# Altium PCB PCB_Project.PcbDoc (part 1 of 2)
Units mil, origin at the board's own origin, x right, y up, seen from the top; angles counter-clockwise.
Board outline 2079.64 x 1653.54 mil, 2 copper layers (Top Layer, Bottom Layer), stack 62 mil thick; 65 components, 34 nets, 154 pads, 107 vias.
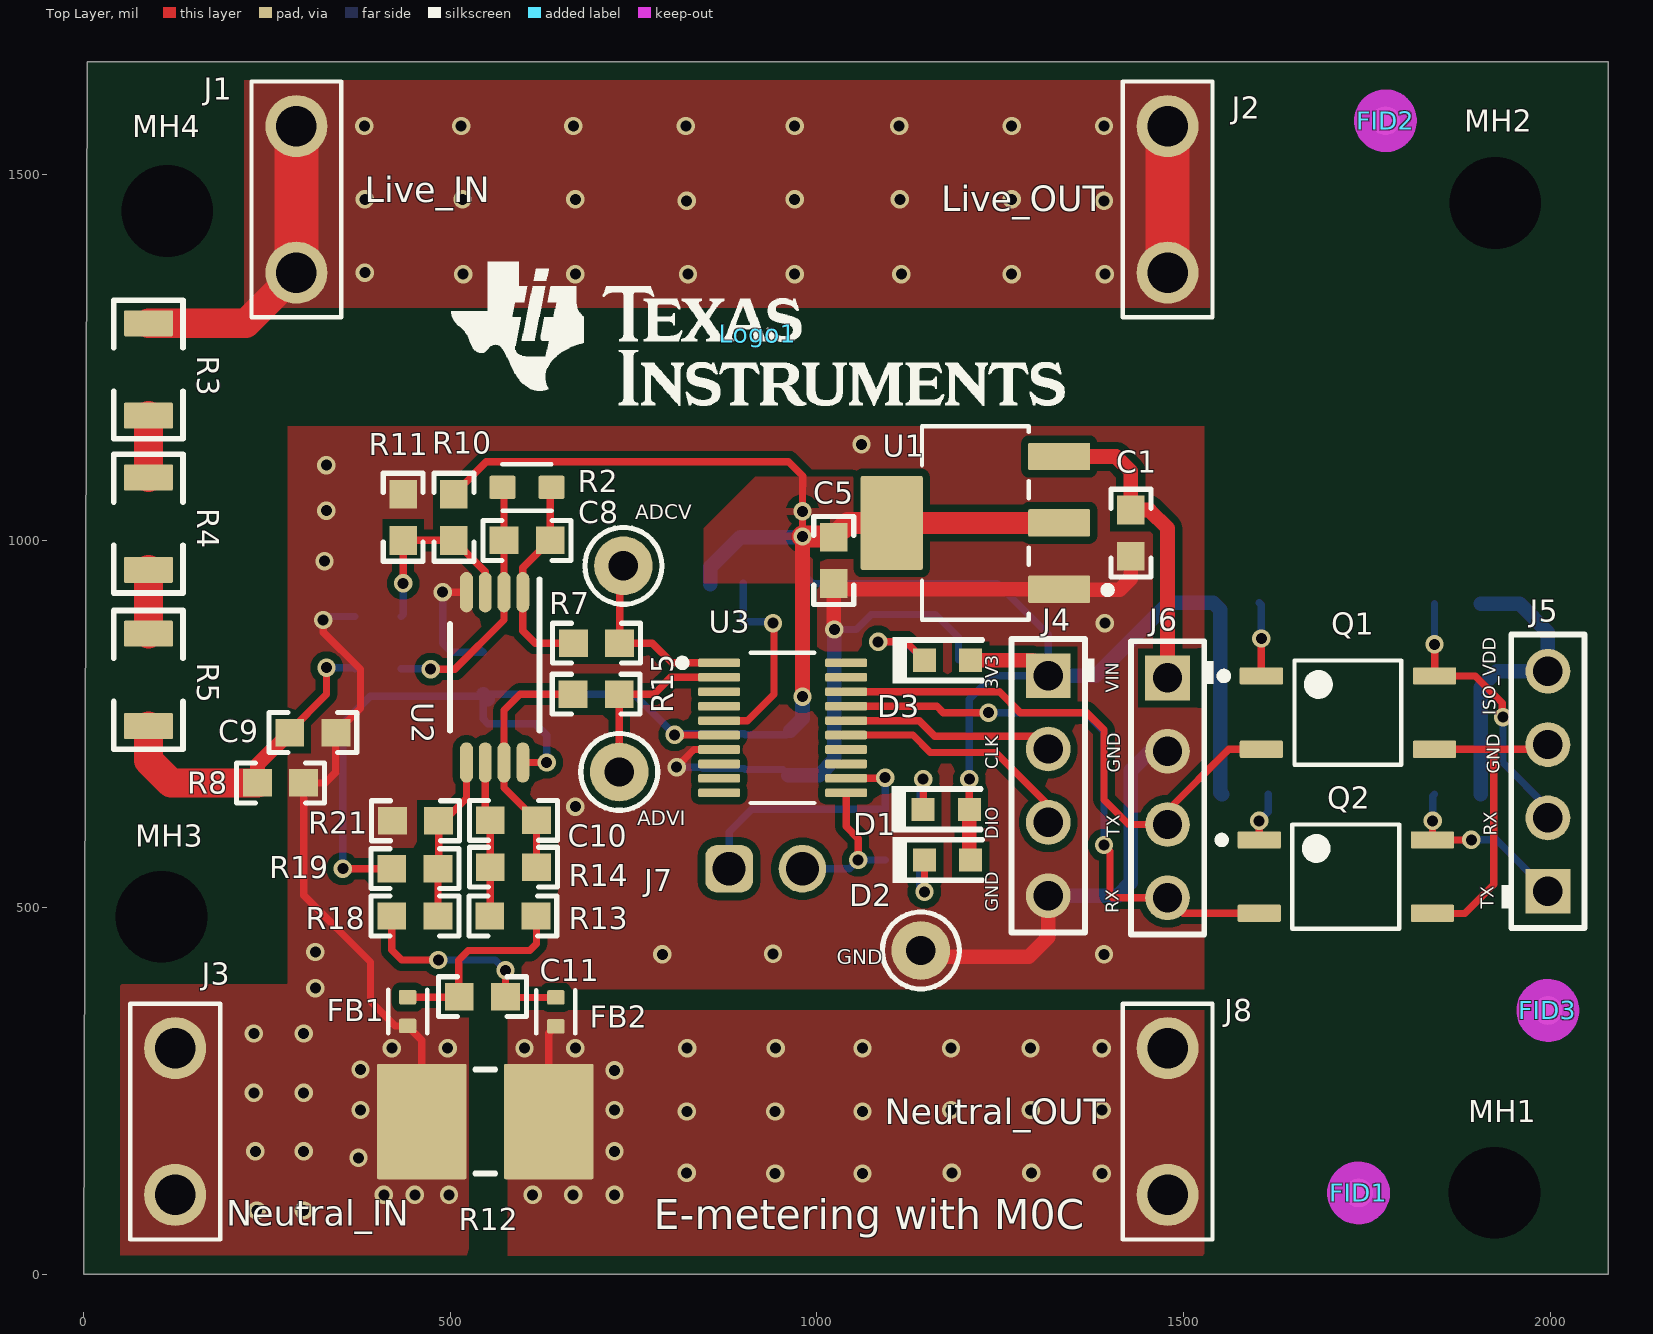
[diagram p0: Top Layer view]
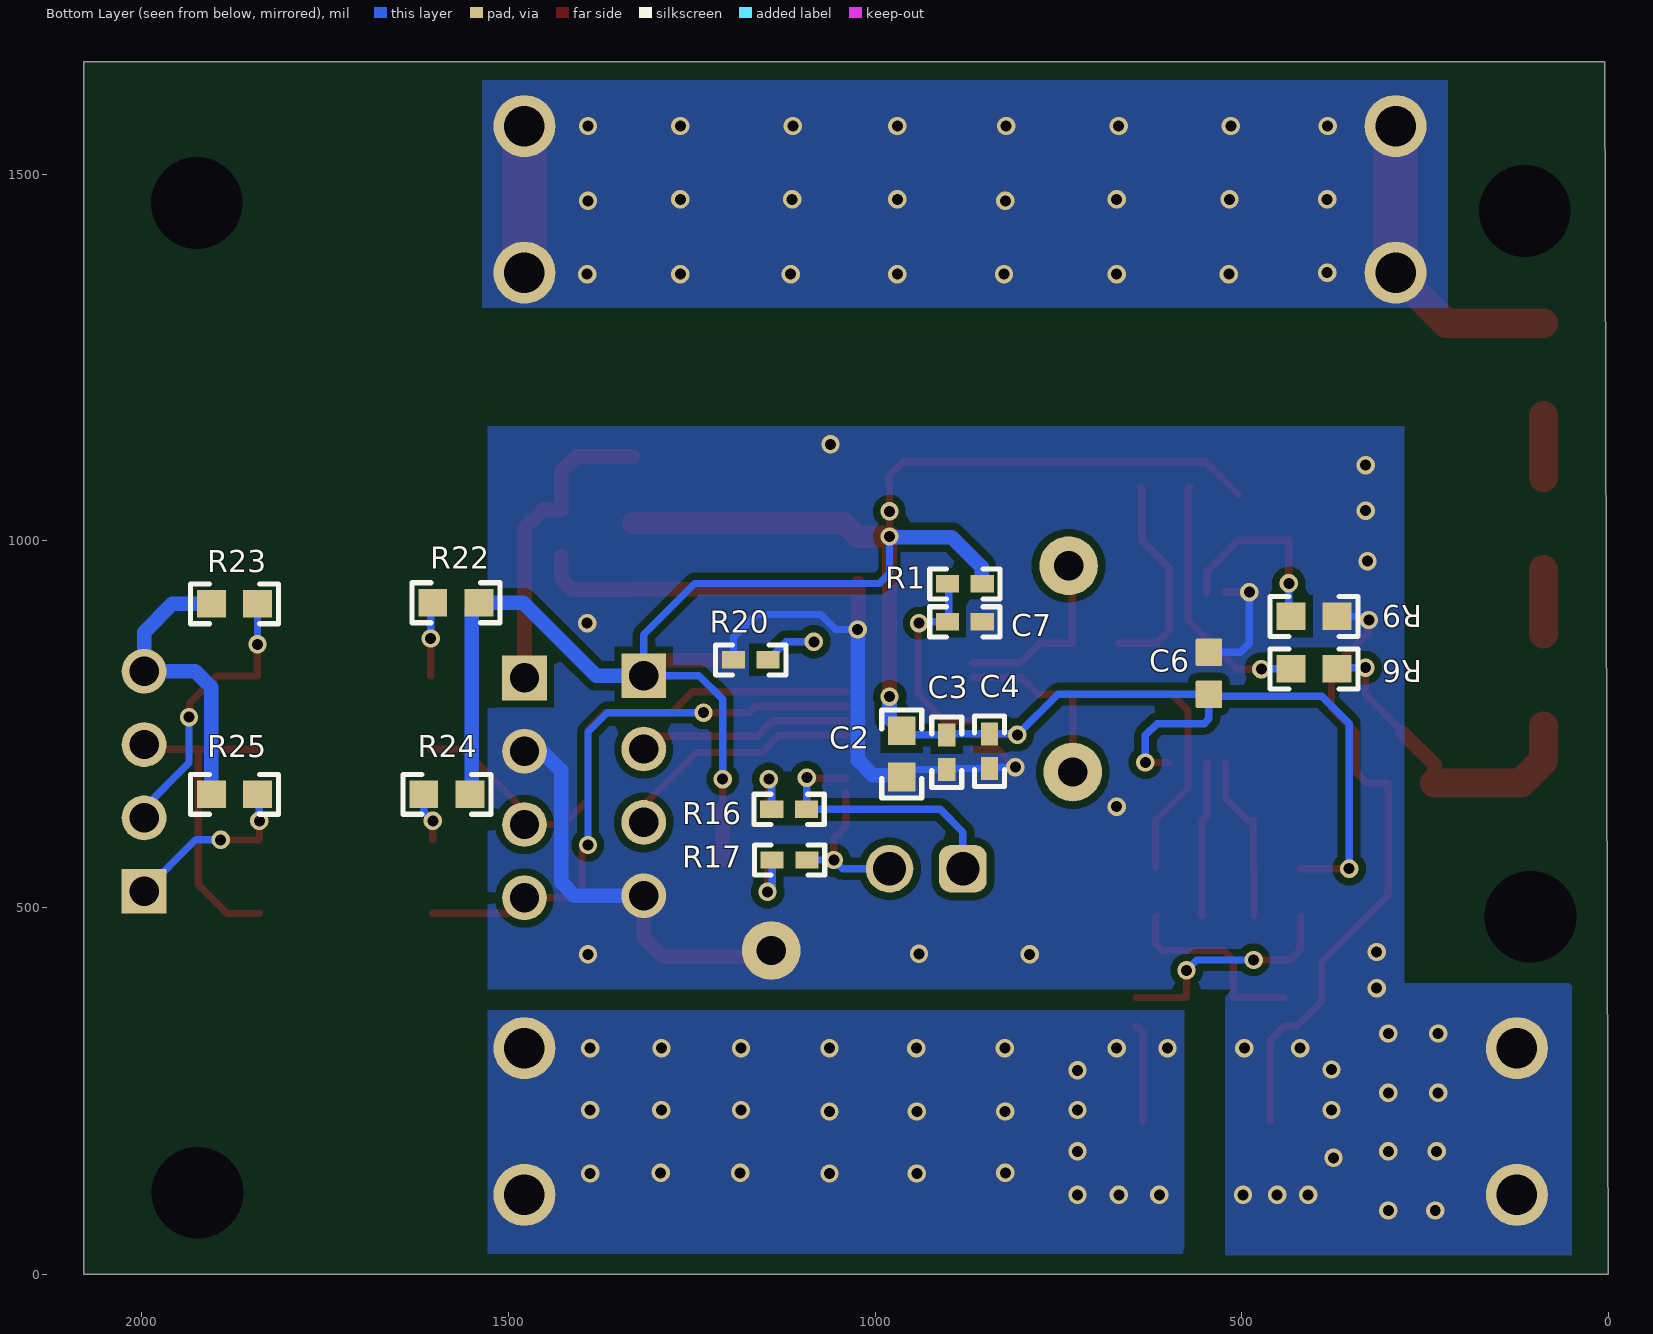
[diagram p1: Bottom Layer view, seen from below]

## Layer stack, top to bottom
Top Solder: solder mask 0.4, Solder Resist, Dk 3.5
Top Layer: signal copper 1.4
Dielectric1: core 59.2, FR-4 High Tg, Dk 4.8
Bottom Layer: signal copper 1.4
Bottom Solder: solder mask 0.4, Solder Resist, Dk 3.5

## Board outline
0,0 4.92,1653.54 2079.64,1653.54 2079.64,0

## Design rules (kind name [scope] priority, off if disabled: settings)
AcuteAngle [All] p1: minimum=4.50000000000000E+0001 checktracksonly=FALSE
AssemblyTestPointUsage [All] p1: valid=2
BoardOutlineClearance BoardOutlineClearance_MountingHoles [OnCopper and InComponentClass('Mounting Holes')] p1: gap=39.37 ignorepadtopadclearanceinfootprint=FALSE
BoardOutlineClearance BoardOutlineClearance_Poly [OnCopper and IsPoly] p2: gap=25 ignorepadtopadclearanceinfootprint=FALSE
BoardOutlineClearance [OnCopper and Not InComponentClass('Logo') and not InComponentClass('FiducialMark') and not InRegion(1000,500,4000,800) and not InPoly] p3: gap=40 ignorepadtopadclearanceinfootprint=FALSE
Clearance Clearance_Keepouts [((IsTrack Or IsArc) And Not InPoly) And IsFree and IsKeepOut vs ((IsTrack Or IsArc) And Not InPoly) And IsFree and IsKeepOut] p1: gap=0 ignorepadtopadclearanceinfootprint=FALSE
Clearance Clearance_Poly [InPolygon] p2: gap=10 ignorepadtopadclearanceinfootprint=TRUE
Clearance Clearance_FiducialMark [IsKeepOut and InComponentClass('FiducialMark') vs IsPad and InComponentClass('FiducialMark')] p3: gap=0 ignorepadtopadclearanceinfootprint=FALSE
Clearance [All] p4: gap=7.87 ignorepadtopadclearanceinfootprint=TRUE
ComponentClearance ComponentClearance_MountingHoles_FiducialMarks [InComponentClass('Mounting Holes') vs InComponentClass('FiducialMark')] p1: gap=50 collisioncheckmode=3 verticalgap=10 showdistances=FALSE
ComponentClearance ComponentClearance_Shunt [InComponentClass('Header') vs InComponentClass('Shunt')] p2: gap=0 collisioncheckmode=3 verticalgap=0 showdistances=FALSE
ComponentClearance ComponentClearance_Logo [InComponentClass('Logo')] p3: gap=30 collisioncheckmode=3 verticalgap=10 showdistances=FALSE
ComponentClearance ComponentClearance_ScrewToNut [(HasFootprint('NY PMS 440 0025 PH')) vs (HasFootprint('Keystone_1902C'))] p4: gap=5 collisioncheckmode=3 verticalgap=10 showdistances=FALSE
ComponentClearance ComponentClearance_MountingHoles [InComponentClass('Mounting Holes')] p5: gap=100 collisioncheckmode=3 verticalgap=100000 showdistances=FALSE
ComponentClearance ComponentClearance_SmallPassives [HasFootprint('0201*') or HasFootprint('0402*') or HasFootprint('0508') or HasFootprint('0603*') or HasFootprint('0612') or HasFootprint('0805*') or HasFootprint('0815*') or HasFootprint('0830*') or HasFootprint('1206*') or HasFootprint('1210*') or HasFootprint('1808*') or HasFootprint('1812*') or HasFootprint('1825*') or HasFootprint('2010*') or HasFootprint('2220*') or HasFootprint('2225*') or HasFootprint('2512*') or HasFootprint('2728*') or HasFootprint('3518*') vs HasFootprint('0201*') or HasFootprint('0402*') or HasFootprint('0508') or HasFootprint('0603*') or HasFootprint('0612') or HasFootprint('0805*') or HasFootprint('0815*') or HasFootprint('0830*') or HasFootprint('1206*') or HasFootprint('1210*') or HasFootprint('1808*') or HasFootprint('1812*') or HasFootprint('1825*') or HasFootprint('2010*') or HasFootprint('2220*') or HasFootprint('2225*') or HasFootprint('2512*') or HasFootprint('2728*') or HasFootprint('3518*')] p6: gap=14.96 collisioncheckmode=3 verticalgap=10 showdistances=FALSE
ComponentClearance ComponentClearance_THtoSMT [IsThruComponent vs IsSMTComponent] p7: gap=30 collisioncheckmode=3 verticalgap=30 showdistances=FALSE
ComponentClearance ComponentClearance_THtoTH [IsThruComponent vs IsThruComponent] p8: gap=20 collisioncheckmode=3 verticalgap=30 showdistances=FALSE
ComponentClearance [All] p9: gap=20 collisioncheckmode=3 verticalgap=10 showdistances=FALSE
DiffPairsRouting [All] p1: maxlimit=100 minlimit=10 mostfreqgap=10 toplayer_minwidth=15 toplayer_maxwidth=15 toplayer_prefwidth=15 bottomlayer_minwidth=15 bottomlayer_maxwidth=15 bottomlayer_prefwidth=15 maxuncoupledlength=1000
FabricationTestPointUsage TestPointUsage [All] p1: valid=2 allowmultiple=FALSE
FabricationTestpoint Testpoint [All] p1: side=3 testpointundercomponent=TRUE minsize=40 maxsize=100 preferedsize=60 minholesize=0 maxholesize=40 preferedholesize=32 testpointgrid=1 allowsidetop=TRUE allowsidebottom=TRUE usegrid=TRUE gridtolerance=0.01
FanoutControl Fanout_LCC [IsLCC] p1: bgadir=Out bgaviamode=Centered fanoutstyle=Auto fanoutdirection=Alternating viagrid=1 // Fanout_LCC (Default Rule)
FanoutControl Fanout_BGA [IsBGA] p2: bgadir=Out bgaviamode=Centered fanoutstyle=Auto fanoutdirection=Alternating viagrid=1 // Fanout_BGA (Default Rule)
FanoutControl Fanout_Default [All] p4: bgadir=Out bgaviamode=Centered fanoutstyle=Auto fanoutdirection=Alternating viagrid=1 // Fanout_Default (Default Rule)
FanoutControl Fanout_Small [(CompPinCount < 5)] p5: bgadir=Out bgaviamode=Centered fanoutstyle=Auto fanoutdirection=OutThenIn viagrid=1 // Fanout_Small (Default Rule)
HoleSize [All] p1: absolutevalues=TRUE maxlimit=251 minlimit=5 maxpercent=80.000 minpercent=20.000
MinimumAnnularRing MinimumAnnularRing_ThermalPadVias [IsVia and InAnyComponent] p1: minimumring=4
MinimumAnnularRing [All] p2: minimumring=4
MinimumSolderMaskSliver MinimumSolderMaskSliver_Logo [InComponentClass('Logo') vs InComponentClass('Logo')] p1: minsoldermaskwidth=0.7
MinimumSolderMaskSliver [All] p2: minsoldermaskwidth=3.94
PlaneConnect [All] p1: planeconnectstyle=Relief reliefexpansion=10 reliefentries=4 reliefconductorwidth=10 reliefairgap=10
PolygonConnect [All] p1: connectstyle=Direct reliefconductorwidth=10 reliefentries=4 polygonreliefangle="90 Angle" airgapwidth=10
RoutingVias ThermalPadVias [IsVia and InAnyComponent] p1: holewidth=7.87 width=19.68 viastyle="Through Hole" minholewidth=7.87 minwidth=19.68 maxholewidth=12.99 maxwidth=23.62
RoutingVias [All] p2: holewidth=15 width=25 viastyle="Through Hole" minholewidth=15 minwidth=25 maxholewidth=15 maxwidth=25
SilkToBoardRegionClearance [Not ((IsComment or IsDesignator) And (Hide <> 'False')) and not InRegion(1000,500,4000,800)] p1:
SilkToSilkClearance SilkToSilkClearance_Pb-FreeLogo [(HasFootprint('Pb-Free_Overlay_Medium') OR HasFootprint('Pb-Free_Overlay_Small')) vs (HasFootprint('Pb-Free_Overlay_Medium') OR HasFootprint('Pb-Free_Overlay_Small'))] p1: silktosilkclearance=0
SilkToSilkClearance [All] p2: silktosilkclearance=0
SilkToSolderMaskClearance SilkToComponentPadClearance [(IsPad or IsFill or IsRegion) and InAnycomponent] p1: minsilkscreentomaskgap=0 clearancetoexposedcopper=TRUE
SilkToSolderMaskClearance "Silk to Solder Mask Opening" [All] p2: minsilkscreentomaskgap=0 clearancetoexposedcopper=FALSE
SolderMaskExpansion [All] p1: expansion=1.97 istentingtop=TRUE
UnRoutedNet [All] p1: checkbadconnections=TRUE
Width [All] p1: maxlimit=100 minlimit=6 preferedwidth=10 checkconnectedcopper=TRUE
14 further rules are at their usual default settings.

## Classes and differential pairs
component class PCB_Project_BlankSheet: ADCI ADCV C1 C2 C3 C4 C5 C6 C7 C8 C9 C10 C11 D1 D2 D3 FB1 FB2 GND J1 J2 J3 J4 J5 J6 J7 J8 Q1 Q2 R1 R2 R3 R4 R5 R6 R7 R8 R9 R10 R11 R12 R13 R14 R15 R16 R17 R18 R19 R20 R21 R22 R23 R24 R25 U1 U2 U3
component class Header: J4 J5 J6 J7
component class FiducialMark: FID1 FID2 FID3
component class PCB_Project_Hardware: FID1 FID2 FID3 Logo1 MH1 MH2 MH3 MH4
component class Logo: Logo1

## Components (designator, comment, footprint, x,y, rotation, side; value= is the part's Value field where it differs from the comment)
ADCV "5000" Keystone5000 736.22,965.81 r90 top (schematic designator TP1)
ADVI "5000" Keystone5000 730.62,684.74 r90 top (schematic designator TP2)
C1 "CGA3E1X7R1V105K080AE" 0603 1428.35,1010.35 r270 top value=1uF
C2 "GRM188R61A106KAALD" 0603 963.83,709.4 r270 bottom value=10uF
C3 "GRM155C81A105KA12D" 0402 902.4,711.63 r270 bottom value=1uF
C4 "04023C103JAT2A" 0402 844.24,712.99 r90 bottom value=0.01uF
C5 "GRM188Z71C225KE43" 0603 1023.08,973.24 r270 top value=2.2uF
C6 "CL10B104KB8NNNC" FP-CL10B104KB8NNNC_0603-IPC_B 544.95,819.38 r90 bottom
C7 "C1005X7R1C103K050BA" 0402 877.66,889.47 r180 bottom value=0.01uF
C8 "C0603C101F5GACTU" 0603 604.93,1000.5 r180 top value=100pF
C9 "C0603C333J3RACTU" 0603 312.66,738.28 r0 top value=0.033uF
C10 "C0603C101F5GACTU" 0603 586.23,618.76 r180 top value=100pF
C11 "C0603C333J3RACTU" 0603 543.91,378.17 r0 top value=0.033uF
D1 "150060VS75000" WL-SMCW_GREEN 1176.48,633.76 r0 top value=Green
D2 "150060YS75000" WL-SMCW_YELLOW 1178.29,564.54 r0 top value=Yellow
D3 "150060RS75000" WL-SMCW_RED 1178.29,837.02 r0 top value=Red
FB1 "74269244182" FP-74269244182_0402-MFG 441.99,357.98 r270 top
FB2 "74269244182" FP-74269244182_0402-MFG 644.14,357.5 r270 top
FID1 "Fiducial" Fiducial10-20 1738.9,110.63 r0 top
FID2 "Fiducial" Fiducial10-20 1775.59,1572.83 r0 top
FID3 "Fiducial" Fiducial10-20 1997.05,359.47 r0 top
GND "5000" Keystone5000 1141.86,441.29 r90 top (schematic designator TP3)
J1 "63824-1" FP-63824-1_CONN_7MM92_3MM11-MFG 290.35,1465.55 r90 top
J2 "63824-1" FP-63824-1_CONN_7MM92_3MM11-MFG 1478.35,1465.55 r90 top
J3 "63824-1" FP-63824-1_CONN_7MM92_3MM11-MFG 125,207.98 r90 top
J4 "PBC04SAAN" Sullins_xxC04SAAN 1315.7,665.93 r270 top
J5 "PBC04SAAN" Sullins_xxC04SAAN 1997.05,672.05 r90 top
J6 "PBC04SAAN" Sullins_xxC04SAAN 1478.35,662.99 r270 top
J7 "61300211121" WURTH_61300211121 930.39,552.72 r0 top
J8 "63824-1" FP-63824-1_CONN_7MM92_3MM11-MFG 1478.35,207.98 r90 top
Logo1 "Texas Instruments" TI_Stacked_Overlay_Small 919.55,1282.48 r0 top
MH1 "MTG_NoPads" NPTH125mil 1924.21,110.63 r0 top
MH2 "MTG_NoPads" NPTH125mil 1925.26,1460.63 r0 top
MH3 "MTG_NoPads" NPTH125mil 106.3,487.45 r0 top
MH4 "MTG_NoPads" NPTH125mil 114.17,1449.8 r0 top
Q1 "ISOM8110DFG" DFG0004A-MFG 1724.41,765.62 r0 top value=80V
Q2 "ISOM8110DFG" DFG0004A-MFG 1721.46,541.97 r0 top value=80V
R1 "RC0402FR-0747KL" 0402 877.66,941.2 r180 bottom value=47.0k
R2 "50k" FP-RT0603BRD0750KL_0603-MFG 604.69,1072.92 r0 top
R3 "TNPV1206330KBEEN" TNPV1206 88.58,1233.56 r90 top value=330k
R4 "TNPV1206330KBEEN" TNPV1206 88.58,1023.34 r90 top value=330k
R5 "TNPV1206330KBEEN" TNPV1206 88.58,810.29 r270 top value=330k
R6 "RT0603BRD0720KL" 0603 401.63,825.31 r0 bottom value=20.0k
R7 "ERJ-3GEY0R00V" 0603 699.57,860.25 r0 top value=0
R8 "RT0603BRD072KL" 0603 268.7,669.75 r180 top value=2.00k
R9 "RT0603BRD0720KL" 0603 401.63,896.79 r0 bottom value=20.0k
R10 "RG1608P-104-B-T5" 0603 505.14,1032 r90 top value=100k
R11 "RG1608P-104-B-T5" 0603 435.85,1032 r270 top value=100k
R12 "CRE2512-FZ-R003E-3" CRE2512-R1_R4 547.85,207.98 r180 top value=0.003
R13 "RT0603DRE071KL" 0603 585.43,488.25 r180 top value=1.00k
R14 "RT0603BRD0720KL" 0603 586.23,554.78 r0 top value=20.0k
R15 "ERJ-3GEY0R00V" 0603 699.12,790.76 r0 top value=0
R16 "RC0402FR-07820RL" 0402 1117.42,633.76 r0 bottom value=820
R17 "RC0402FR-07820RL" 0402 1116.86,564.54 r0 bottom value=820
R18 "RT0603DRE071KL" 0603 451.83,488.25 r0 top value=1.00k
R19 "PAT0603E4002BST1" 0603 451.83,552.72 r0 top value=40.0k
R20 "RC0402FR-07820RL" 0402 1169.57,837.58 r180 bottom value=820
R21 "PAT0603E4002BST1" 0603 452.81,618.08 r0 top value=40.0k
R22 "RT0603DRE071KL" 0603 1571.85,915.46 r0 bottom value=1.00k
R23 "RT0603DRE071KL" 0603 1873.84,914 r0 bottom value=1.00k
R24 "RT0603DRE071KL" 0603 1584.18,654.26 r0 bottom value=1.00k
R25 "RT0603DRE071KL" 0603 1873.84,654.26 r0 bottom value=1.00k
U1 "TLV76133DCYR" DCY0004A-MFG 1216.41,1024.35 r180 top
U2 "TLV9062IPWR" PW0008A_N 560.64,813.73 r270 top
U3 "MSPM0C1104SDGS20R" DGS0020A-MFG 953.39,744.84 r0 top

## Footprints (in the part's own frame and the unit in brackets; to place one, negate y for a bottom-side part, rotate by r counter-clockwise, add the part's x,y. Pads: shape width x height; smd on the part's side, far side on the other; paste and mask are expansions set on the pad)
0402 [mm] "0402 from SM-752 data"
  rect 0.8x0.6 smd: 1(-0.6,0) 2(0.6,0)
  silkscreen extent -1.22,-0.52 1.22,0.52, body extent -0.55,-0.3 0.55,0.3, height 0.6
0603 [mm] "0603 from SM-752 data"
  rect 1x0.95 smd: 1(-0.8,0) 2(0.8,0)
  silkscreen extent -1.52,-0.69 1.52,0.69, body extent -0.87,-0.47 0.87,0.47, height 1
CRE2512-R1_R4 [mm] "SMD, 2-Leads, Body 6.45x3.35mm"
  rrect3% 3.1x4 smd: 1(-2.2,0) 2(2.2,0)
  silkscreen extent -0.35,-1.8 0.35,1.8, body extent -3.32,-1.77 3.33,1.78, height 0.9
DCY0004A-MFG [mm]
  rrect11% 2.15x0.95 smd paste+0 mask+0: 1(-2.9,2.3) 2(-2.9,0) 3(-2.9,-2.3)
  rrect5% 2.15x3.25 smd paste+0 mask+0: 4(2.9,0)
  silkscreen extent -4.7,-3.35 1.85,3.35, body extent -4.08,-3.45 4.08,3.45, height 0.25
DFG0004A-MFG [mm]
  rrect17% 1.5x0.6 smd paste+0 mask+0: 1(-3,1.27) 2(-3,-1.27) 3(3,-1.27) 4(3,1.27)
  silkscreen extent -4.42,-1.81 1.85,1.81, body extent -3.85,-2.05 3.85,2.05, height 0.25
DGS0020A-MFG [mm]
  rrect33% 1.45x0.3 smd paste+0 mask+0: 1(-2.2,2.25) 2(-2.2,1.75) 3(-2.2,1.25) 4(-2.2,0.75) 5(-2.2,0.25) 6(-2.2,-0.25) 7(-2.2,-0.75) 8(-2.2,-1.25) 9(-2.2,-1.75) 10(-2.2,-2.25) 11(2.2,-2.25) 12(2.2,-1.75) 13(2.2,-1.25) 14(2.2,-0.75) 15(2.2,-0.25) 16(2.2,0.25) 17(2.2,0.75) 18(2.2,1.25) 19(2.2,1.75) 20(2.2,2.25)
  silkscreen extent -3.6,-2.6 1.1,2.6, body extent -3.03,-2.85 3.03,2.85, height 0.25
Fiducial10-20 [mm]
  round 1 smd mask+0.5: 1(0,0)
  Top Layer keep-out circle w1.178: c0,0 r0.5
FP-63824-1_CONN_7MM92_3MM11-MFG [mm]
  round 2.15 hole 1.4 paste-1000 mask+0: 1(-2.54,0) 1(2.54,0)
  silkscreen extent -4.09,-1.56 4.09,1.56, body extent -3.96,-1.54 3.96,1.54, height 10.88
FP-74269244182_0402-MFG [mm]
  rrect20% 0.5x0.6 smd paste+0 mask+0: 1(-0.5,0) 2(0.5,0)
  silkscreen extent -0.75,-0.67 0.75,0.67, body extent -0.5,-0.25 0.5,0.25, height 0.55
FP-CL10B104KB8NNNC_0603-IPC_B [mil]
  rrect11% 37.72x35.91 smd paste+0 mask+0: 1(-28.62,0) 2(28.62,0)
  body extent -31,-16 31,16, height 35
FP-RT0603BRD0750KL_0603-MFG [mm]
  rrect13% 0.9x0.8 smd paste+0 mask+0: 1(-0.85,0) 2(0.85,0)
  silkscreen extent -0.85,-0.81 0.86,0.8, body extent -1.4,-0.55 1.4,0.55, height 0.25
Keystone5000 [mil] "For Keystone 500x miniature loop terminals"
  round 80 hole 40: 1(0,0)
  silkscreen extent -52,-52 52,52, body extent -49,-49 49,49, height 182
NPTH125mil [mil]
  round 120 hole 125 unplated mask+15: 1(0,0)
PW0008A_N [mm] "TSOP, 8-Leads, Body 3x4.4mm, Pitch 0.65mm, IPC Medium Density"
  oval 1.4x0.45 smd: 1(-2.95,0.975) 2(-2.95,0.325) 3(-2.95,-0.325) 4(-2.95,-0.975) 5(2.95,-0.975) 6(2.95,-0.325) 7(2.95,0.325) 8(2.95,0.975)
  silkscreen extent -3.4,-1.55 1.85,1.55, body extent -3.21,-1.5 3.21,1.5, height 1.2
Sullins_xxC04SAAN [mm] "Header, 2.54 mm, 4x1, TH"
  rect 1.55x1.55 hole 1.016: 1(-3.81,0)
  round 1.55 hole 1.016: 2(-1.27,0) 3(1.27,0) 4(3.81,0)
  silkscreen extent -5.08,-1.27 5.08,1.6, body extent -5.08,-1.27 5.08,1.27, height 8.38
TI_Stacked_Overlay_Small [mil]
  silkscreen extent -418,-98 418,98
TNPV1206 [mm] "VISHAY"
  rrect11% 0.9x1.7 smd: 1(-1.6,0) 2(1.6,0)
  silkscreen extent -2.4,-1.2 2.4,1.2, body extent -1.67,-0.87 1.67,0.87, height 0.65
WL-SMCW_GREEN [mm] "WURTH"
  rect 0.8x0.8 smd: 1(-0.8,0) 2(0.8,0)
  silkscreen extent -1.9,-0.8 1.2,0.8, body extent -0.85,-0.45 0.85,0.45, height 0.8
WL-SMCW_RED [mm] "WURTH"
  rect 0.8x0.8 smd: 1(-0.8,0) 2(0.8,0)
  silkscreen extent -1.9,-0.8 1.2,0.8, body extent -0.85,-0.45 0.85,0.45, height 0.8
WL-SMCW_YELLOW [mm] "WURTH"
  rect 0.8x0.8 smd: 1(-0.8,0) 2(0.8,0)
  silkscreen extent -1.9,-0.8 1.2,0.8, body extent -0.85,-0.45 0.85,0.45, height 0.8
WURTH_61300211121 [mm] "Header, 2.54mm, 2x1, TH"
  rrect50% 1.65x1.65 hole 1.15: 1(-1.27,0)
  round 1.65 hole 1.15: 2(1.27,0)
  body extent -2.54,-1.27 2.54,1.27, height 8.54

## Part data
ADCV ADVI GND: library part CMP-0055137-2, "Test Point, Miniature, Red, TH", Color=Red, Manufacturer="Keystone Electronics", Supplier Part Number 1=36-5000-ND
C1: library part CMP-0081259-1, "CAP, CERM, 1 µF, 35 V,+/- 10%, X7R, AEC-Q200 Grade 1, 0603", Cap_Case=0603, Manufacturer=TDK, Supplier Part Number 1=445-174339-1-ND, TempCo=X7R, Tolerance_%=10%, Value2=35V, ValueDisplayed=1µF
C2: library part CMP-0086193-1, "CAP, CERM, 10 µF, 10 V,+/- 10%, X5R, 0603", Cap_Case=0603, Manufacturer=MuRata, TempCo=X5R, Tolerance_%=10%, Value2=10V, ValueDisplayed=10µF
C3: library part CMP-0064971-2, "CAP, CERM, 1 uF, 10 V,+/- 10%, X6S, 0402", Cap_Case=0402, Manufacturer=MuRata, Supplier Part Number 1=490-12699-1-ND, TempCo=X6S, Tolerance_%=10%, Value1=Unknown, Value2=10V, ValueDisplayed=1uF
C4: library part CMP-0085568-1, "CAP, CERM, 0.01 µF, 25 V,+/- 5%, X7R, 0402", Cap_Case=0402, Manufacturer=AVX, TempCo=X7R, Tolerance_%=5%, Value2=25V, ValueDisplayed=0.01µF
C5: library part CMP-0007499-1, "CAP, CERM, 2.2 uF, 16 V, +/- 10%, X7R, 0603", Cap_Case=0603, Manufacturer=MuRata, Supplier Part Number 1=81-GRM188Z71C225KE3D, TempCo=X7R, Tolerance_%=10%, Value1=Unknown, Value2=16V, ValueDisplayed=2.2uF
C6: library part CMP-0087079-1, "CAP CER 0.1UF 50V X7R 0603", Manufacturer=Samsung, TempCo=15%, Tolerance_%=10%
C7: library part CMP-0006292-2, "CAP, CERM, 0.01 uF, 16 V, +/- 10%, X7R, 0402", Cap_Case=0402, Manufacturer=TDK, Supplier Part Number 1=445-1262-1-ND, TempCo=X7R, Tolerance_%=10%, Value1="0.0623 ohm", Value2=16V, ValueDisplayed=0.01uF
C8 C10: library part CMP-0080091-1, "CAP, CERM, 100 pF, 50 V,+/- 1%, C0G/NP0, 0603", Cap_Case=0603, Manufacturer=Kemet, Supplier Part Number 1=399-7819-1-ND, TempCo=C0G/NP0, Tolerance_%=1%, Value2=50V, ValueDisplayed=100pF
C9 C11: library part CMP-0006923-4, "CAP, CERM, 0.033 uF, 25 V, +/- 5%, X7R, 0603", Cap_Case=0603, Manufacturer=Kemet, Supplier Part Number 1=399-9068-1-ND, TempCo=X7R, Tolerance_%=5%, Value1=Unknown, Value2=25V, ValueDisplayed=0.033uF
D1: library part CMP-0002894-2, "LED, Green, SMD", Color=green, Manufacturer="Wurth Elektronik", Value1=W, Value2=2V
D2: library part CMP-0002892-3, "LED, Yellow, SMD", Color=yellow, Manufacturer="Wurth Elektronik", Value1=W, Value2=2V
D3: library part CMP-0002947-2, "LED, Red, SMD", Color=Red, Manufacturer="Wurth Elektronik", Power_TotalModule=72mW, Supplier Part Number 1=732-4978-1-ND, Value1=0.072W, Value2=2V
FB1 FB2: library part CMP-0091663-1, "1.8 kOhms @ 100MHz 1 Power, Signal Line Ferrite Bead 0402 (1005 Metric) 210mA 2.1Ohm", Digikey Part Number=732-74269244182CT-ND, Impedance At Frequency="1800Ω @ 100MHz", Manufacturer="Wurth Electronics", Mouser Part Number=710-74269244182, Operating Temperature Range="-55°C to +125°C", Test Frequency=1GHz, Tolerance_%=25%
FID1 FID2 FID3: library part CMP-0077181-1, "Fiducial mark.  There is nothing to buy or mount.", Manufacturer=N/A
J1 J2 J3 J8: library part CMP-0089624-1, Current_A=20A, Digikey Part Number=A29938CT-ND, Manufacturer="TE Connectivity", Mouser Part Number=571-638241, Operating Temperature Range="-40°C to +105°C"
J4 J5 J6: library part CMP-0054583-1, "Header, 2.54 mm, 4x1, Gold, TH", Color=Black, Current_A=3A, Manufacturer="Sullins Connector Solutions", Supplier Part Number 1=S1011E-04-ND, Voltage_V=1.8kV
J7: library part CMP-0054794-2, "Header, 2.54 mm, 2x1, Gold, TH", Color=Black, Manufacturer="Wurth Elektronik", Supplier Part Number 1=732-5315-ND
Logo1: library part CMP-0074838-1, "Texas Instrument Corporate Signature"
MH1 MH2 MH3 MH4: library part CMP-0078424-2, "PCB Mounting Hole, No Pad", Manufacturer=Any, PartNumber=N/A
Q1 Q2: library part CMP-0098363-1, "3.75-kVRMS, Single-Channel Opto-Emulator with Transistor Output", Emiiter Collector Voltage=7V, Forward Current=10mA, Manufacturer="Texas Instruments", Operating Temperature Range="to +150°C", Power_TotalModule=200mW, Voltage_Isolation_Vrms=3750Vrms
R1: library part CMP-0026737-1, "RES, 47.0 k, 1%, 0.0625 W, 0402", Manufacturer="Yageo America", Power_W=62.5mW, Supplier Part Number 1=311-47.0KLRCT-ND, TempCo="100 ppm/C", Tolerance_%=1%, Value2=0.0625W, Value_Code=47k0, ValueDisplayed=47.0k
R2: library part CMP-0096502-1, "High Precision-High Stability Chip Resistor Thin Film 0603 50kOhm 0.1% Paper T/R", Digikey Part Number=13-RT0603BRD0750KLCT-ND, Manufacturer=Yageo, Mouser Part Number=603-RT0603BRD0750KL, Operating Temperature Range="-55°C to +155°C", Part Number=RT0603BRD0750KL, Power_W=100mW, TempCo=25ppm/°C, Tolerance_%=0.1%
R3 R4 R5: library part CMP-0018811-2, "RES, 330 k, 0.1%, 1 W, 1206", Manufacturer="Vishay Draloric", Power_W=1W, Supplier Part Number 1=541-2312-1-ND, TempCo="25 ppm/C", Tolerance_%=0.1%, Value_Code=330k
R6 R9 R14: library part CMP-0023931-3, "RES, 20.0 k, 0.1%, 0.1 W, 0603", Manufacturer="Yageo America", Power_W=100mW, TempCo="25 ppm/C", Tolerance_%=0.1%, Value2=0.1W, Value_Code=20k0, ValueDisplayed=20.0k
R7 R15: library part CMP-0025874-2, "RES, 0, 5%, 0.1 W, 0603", Manufacturer=Panasonic, Power_W=100mW, Supplier Part Number 1=P0.0GCT-ND, TempCo="600 ppm/C", Tolerance_%=5%, Value2=0.1W, Value_Code=0000, ValueDisplayed=0
R8: library part CMP-0024089-2, "RES, 2.00 k, 0.1%, 0.1 W, 0603", Manufacturer="Yageo America", Power_W=100mW, Supplier Part Number 1=603-RT0603BRD072KL, TempCo="25 ppm/C", Tolerance_%=0.1%, Value2=0.1W, Value_Code=2k00, ValueDisplayed=2.00k
R10 R11: library part CMP-0023405-1, "RES, 100 k, 0.1%, 0.1 W, 0603", Manufacturer="Susumu Co Ltd", Power_W=100mW, Supplier Part Number 1=RG16P100KBCT-ND, TempCo="25 ppm/C", Tolerance_%=0.1%, Value2=0.1W, Value_Code=100k
R12: library part CMP-0015750-2, "RES, 0.003, 1%, 3 W, AEC-Q200 Grade 0, 2512", Manufacturer=Bourns, Power_W=3W, Supplier Part Number 1=CRE2512-FZ-R003E-3CT-ND, TempCo="50 ppm/C", Tolerance_%=1%, Value_Code=3L000, ValueDisplayed=0.003
R13 R18 R22 R23 R24 R25: library part CMP-0024852-1, "RES, 1.00 k, 0.5%, 0.1 W, 0603", Manufacturer="Yageo America", Power_W=100mW, TempCo="50 ppm/C", Tolerance_%=0.5%, Value2=0.1W, Value_Code=1k00, ValueDisplayed=1.00k
R16 R17 R20: library part CMP-0026743-1, "RES, 820, 1%, 0.063 W, 0402", Manufacturer="Yageo America", Power_W=63mW, Supplier Part Number 1=311-820LRCT-ND, TempCo="100 ppm/C", Tolerance_%=1%, Value2=0.063W, Value_Code=820R, ValueDisplayed=820
R19 R21: library part CMP-0860025-1, "RES, 40.0 k, 0.1%, 0.15 W, AEC-Q200 Grade 0, 0603", Manufacturer="Vishay Thin Film", Power_W=150mW, TempCo="25 ppm/C", Tolerance_%=0.1%, Value2=0.15W, Value_Code=40k0, ValueDisplayed=40.0k
U1: library part CMP-0122558-1, "1-A 16-V high-PSRR linear voltage regulator 4-SOT-223 -40 to 125", Digikey Part Number=296-TLV76133DCYRCT-ND, Dropout Voltage=0.9V, Manufacturer="Texas Instruments", Max Supply Voltage=16V, Min Supply Voltage=4.8V, Mouser Part Number=595-TLV76133DCYR, Nominal Supply Current=65uA, Operating Temperature Range="-40°C to +125°C", Output Voltage=3.3V
U2: library part CMP-0084065-1, "10-MHz, Low-Noise, RRIO, CMOS Operational Amplifier for Cost-Sensitive Systems, PW0008A (TSSOP-8)", Alternate Manufacturer="Texas Instruments", Operating Temperature Range="-40 to 125 C", Rating=Catalog
U3: library part CMP-0121923-1, "Mixed-Signal Microcontrollers", Frequency_Fixed=24MHz, Manufacturer="Texas Instruments", Max Supply Voltage=3.6V, Min Supply Voltage=1.62V, Operating Temperature Range="-40°C to +125°C"

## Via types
v1: diameter 25, hole 15, Top Layer to Bottom Layer, tented both sides, 107 vias

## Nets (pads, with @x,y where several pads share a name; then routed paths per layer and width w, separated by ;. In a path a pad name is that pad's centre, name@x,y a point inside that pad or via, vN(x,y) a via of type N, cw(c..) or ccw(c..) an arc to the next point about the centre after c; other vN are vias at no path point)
A_LIN_IN: J1.1 J2.1 R3.2 | length 630.3
  Top Layer w40: R3.2@88.58,1296.56 221.36,1296.56 J1.1@290.35,1365.55
  Top Layer w60: J1.1@290.35,1365.55 J1.1@290.35,1565.55 ; J2.1@1478.35,1365.55 J2.1@1478.35,1565.55
  other v1: 517.69,1363.57 670.72,1363.57 824.33,1363.57 969.75,1363.57 1115.3,1363.57 1265.7,1363.57 1392.79,1363.57 383.58,1365.55 822.58,1463.58 1391.73,1463.58 383.58,1465.55 516.76,1465.55 670.72,1465.55 969.75,1465.55 1113.33,1465.55 1265.7,1465.55 382.93,1565.55 514.9,1565.55 668.08,1565.55 821.5,1565.55 969.75,1565.55 1112.31,1565.55 1265.7,1565.55 1391.73,1565.55
A_Netural_IN: C1.2 C2.2 C3.2 C4.1 C5.2 C6.2 C7.2 C9.2 FB1.2 GND.1 J3.1 J4.4 J6.2 R8.1 R9.1 R11.1 R12.2 R20.1 R21.1 U1.1 U2.4 U3.7 | length 2829.8
  Top Layer w10: v1(326.89,891.95) 326.89,875.36 377.62,824.63 377.62,771.74 C9.2@344.16,738.28 344.16,684.18 329.72,669.75 R8.1@300.2,669.75 300.2,516.56 391.32,425.44 391.32,371.99 425.02,338.29 FB1.2@441.99,338.29 ; FB1.2@441.99,337.95 461.23,318.7 R12.2@461.23,207.98 ; v1(489.78,929.88) U2.4@522.26,929.88 ; v1(808.98,691.34) 808.61,691.34 832.58,715.31 U3.7@866.77,715.31
  Top Layer w20: v1(1023.81,878.95) 1023.08,879.68 C5.2@1023.08,941.74 1031.02,933.8 U1.1@1330.58,933.8 1330.98,933.4 1413.35,933.4 1428.35,948.39 C1.2@1428.35,978.85 ; GND.1@1141.86,441.29 1150.36,432.79 1289.24,432.79 1315.7,459.24 J4.4@1315.7,515.93
  Bottom Layer w10: v1(326.89,891.95) 331.73,896.79 R9.1@370.14,896.79 ; v1(489.78,929.88) 489.78,860.25 502.03,848 C6.2@544.95,848 C6.2@541.33,851.62 ; v1(808.98,691.34) 842.27,691.34 C4.1@844.24,689.37 901.03,689.37 C3.2@902.4,688.01 953.73,688.01 961.43,680.31 C2.2@963.83,677.91 ; v1(1023.81,878.95) 1053.87,878.95 1074.42,899.51 1161.95,899.51 1193.19,868.27 R20.1@1193.19,837.58
  Bottom Layer w20: C2.2@961.43,680.31 1003.09,680.31 1023.81,701.03 v1(1023.81,878.95) ; J4.4@1315.7,515.93 1410.25,515.93 1428.35,534.02 1428.35,686.65 1454.69,712.99 J6.2@1478.35,712.99
  other v1: 236.22,86.61 300.2,86.61 409.53,107.98 451.83,107.98 498.37,107.98 375,158.46 234.25,167.32 300.2,167.32 377.62,223.73 232.28,247.05 300.2,247.05 377.62,278.85 420.55,307.98 496.67,307.98 232.28,327.98 300.2,327.98 316.07,389.73 789.44,435.96 940.23,436.73 1391.73,435.96 316.07,439.11 670.72,637.46 1392.79,887.52 328.68,972.25 331.08,1041.13 331.08,1103.09 1061,1131.54
A_Netural_OUT: FB2.2 J8.1 R12.1 | length 133.9
  Top Layer w10: R12.1@634.46,207.98 634.46,328.14 FB2.2@644.14,337.82
  other v1: 612.43,107.98 667.63,107.98 724.04,107.98 943.17,137.11 1062.4,137.11 1388.65,137.11 822.43,138.1 1184.04,138.1 1292.61,138.1 724.04,167.32 822.86,221.64 943.17,221.64 1062.4,221.64 724.04,223.73 1183,223.71 1291.59,223.71 1388.65,223.71 724.04,277.86 601.47,307.98 670.72,307.98 823.22,307.98 943.9,307.98 1062.4,307.98 1183,307.98 1291.41,307.98 1388.65,307.98
ACT: J7.1 R16.1 U3.12 | length 373.2
  Top Layer w10: U3.12@1040,675.94 1091.42,675.94 1092.3,676.83 v1(1093.23,676.83)
  Bottom Layer w10: J7.1@880.39,552.72 880.39,602.72 911.42,633.76 R16.1@1093.8,633.76 1093.23,634.32 v1(1093.23,676.83)
ADC_I: ADVI.1 R15.2 U3.2 | length 251.7
  Top Layer w10: ADVI.1@730.62,684.74 R15.2@730.62,790.76 777.95,790.76 800.93,813.73 U3.2@866.77,813.73
ADC_V: ADCV.1 R7.2 U3.1 | length 254.5
  Top Layer w10: ADCV.1@736.22,965.81 731.07,960.65 R7.2@731.07,860.25 775.77,860.25 802.6,833.42 U3.1@866.77,833.42
GLED: D1.1 R16.2 | length 84
  Top Layer w10: D1.1@1144.98,633.76 v1(1144.98,674.95)
  Bottom Layer w10: R16.2@1141.04,633.76 1141.04,671.02 v1(1144.98,674.95)
ISO_3V3: J5.4 R23.2 R25.2 | length 407.8
  Bottom Layer w20: R25.2@1905.34,654.26 1905.34,800.3 1927.09,822.05 J5.4@1997.05,822.05 1997.05,875.34 1958.39,914 R23.2@1905.34,914
ISO_GND: J5.3 Q1.3 Q2.3 | length 441.8
  Top Layer w10: Q2.3@1839.57,491.97 1839.83,491.7 1883.78,491.7 1923.19,531.12 1923.19,715.62 ; Q1.3@1842.52,715.62 1923.19,715.62 ; J5.3@1997.05,722.05 1990.62,715.62 1923.19,715.62
NetC7_1: C7.1 R1.1 U3.5 | length 281.4
  Top Layer w10: U3.5@866.77,754.68 905.5,754.68 941.69,790.87 v1@941.69,889.64
  Bottom Layer w10: C7.1@899.63,888.97 R1.1@899.63,941.9 ; C7.1@901.28,889.47 938.28,889.47 v1(940.23,887.52)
